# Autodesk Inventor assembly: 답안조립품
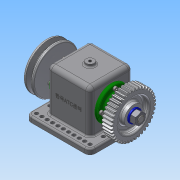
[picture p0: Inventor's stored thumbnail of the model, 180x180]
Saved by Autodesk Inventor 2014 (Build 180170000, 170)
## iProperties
Created: 2018-11
Part Number: 답안조립품
Document SubType Name: Assembly
Designer: NET
Author: NET
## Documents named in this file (13)
- C:\Users\NET\Desktop\481107V1006\답안조립품.iam
- C:\Users\NET\Desktop\481107V1006\본체.ipt
- C:\Users\NET\Desktop\481107V1006\커버.ipt
- C:\Users\NET\Desktop\481107V1006\볼트 M4.ipt
- C:\Users\NET\Desktop\481107V1006\베어링 6203.ipt
- C:\Users\NET\Desktop\481107V1006\오일 실 26 38 8.ipt
- C:\Users\NET\Desktop\481107V1006\축.ipt
- C:\Users\NET\Desktop\481107V1006\키 5x5x12.ipt
- C:\Users\NET\Desktop\481107V1006\스퍼기어.ipt
- C:\Users\NET\Desktop\481107V1006\부시.ipt
- C:\Users\NET\Desktop\481107V1006\와셔 12x24.ipt
- C:\Users\NET\Desktop\481107V1006\너트 M12x1.25.ipt
- C:\Users\NET\Desktop\481107V1006\V벨트풀리.ipt
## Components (1 placed, 1 different names)
1. V벨트풀리:1 — 각도:1
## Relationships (1: Angle 1)
- 각도:1 [Angle]: V벨트풀리:1
